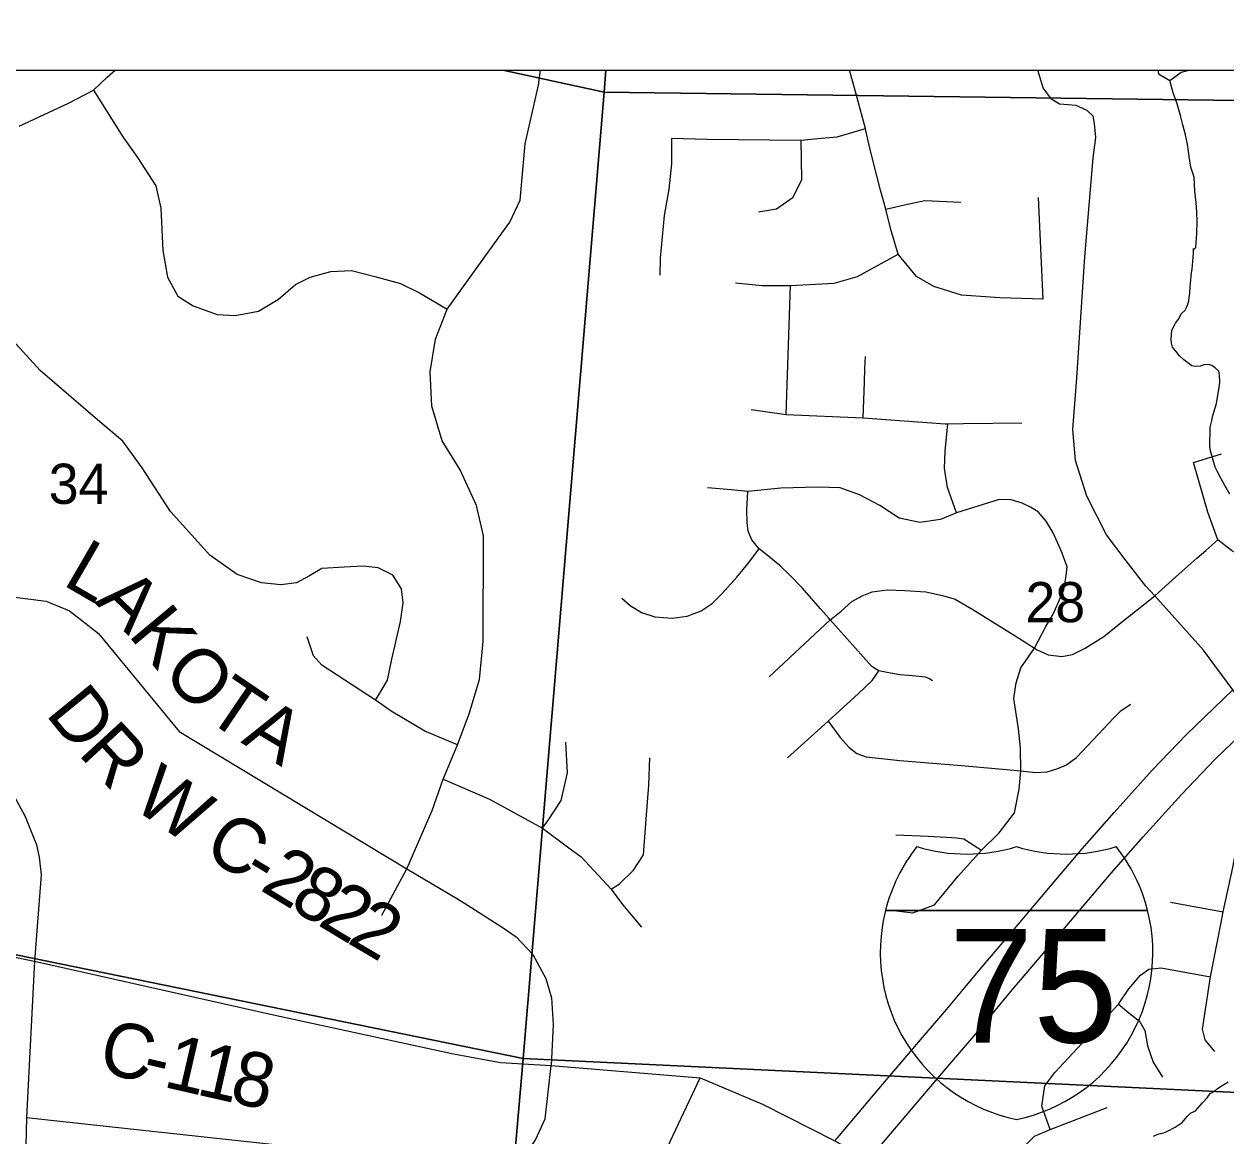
# Model space of a CAD drawing. Extents: x 0 to 34, y 0 to 22.
# Drawn here: x 6.065 to 7.317, y 17.049 to 18.207 of the extents above; entities that cross this region are included whole.
import ezdxf

# ---------------------------------------------------------------- set-up
doc = ezdxf.new("R2010")
doc.units = 0
for name, color, linetype in [('GM_X_County_Road', 7, 'Continuous'), ('GM_X_County_Road_Text', 7, 'Continuous'), ('GM_X_Interstate_Route', 7, 'Continuous'), ('GM_X_Interstate_Shield', 7, 'Continuous'), ('GM_X_Minor_River', 7, 'Continuous'), ('GM_X_Section', 7, 'Continuous'), ('GM_X_Section_Text', 7, 'Continuous'), ('GM_X_Township_Road', 7, 'Continuous'), ('SH_Text', 7, 'Continuous')]:
    doc.layers.add(name, color=color, linetype=linetype)

msp = doc.modelspace()

# ---------------------------------------------------------------- linework, layer by layer
at = {"layer": 'GM_X_County_Road'}
for points in [[(6.0466, 17.6112), (6.0876, 17.6058), (6.1121, 17.5959), (6.1422, 17.5721), (6.2262, 17.4703), (6.4637, 17.327), (6.5163, 17.296), (6.5237, 17.2912)], [(6.05, 17.4113), (6.0658, 17.3817), (6.0778, 17.352), (6.0803, 17.3393), (6.0827, 17.3208), (6.0757, 17.231), (6.0674, 17.0682), (6.0665, 17.0388)], [(5.5717, 17.3314), (5.8034, 17.2861), (6.0757, 17.231)], [(6.5237, 17.2912), (6.5628, 17.2662), (6.5774, 17.2562), (6.595, 17.2378), (6.6085, 17.213), (6.6145, 17.1929), (6.6161, 17.1648), (6.6139, 17.1224)], [(6.0757, 17.231), (6.3248, 17.175), (6.5122, 17.1344), (6.5614, 17.1253), (6.6139, 17.1224), (6.7693, 17.1094)], [(6.4586, 16.8305), (6.5073, 16.9065), (6.5468, 16.9654), (6.5664, 16.9923), (6.5837, 17.0228), (6.5978, 17.0449), (6.6079, 17.0666), (6.6139, 17.1224)], [(6.7693, 17.1094), (6.8344, 17.0818), (6.9097, 17.0436), (6.9449, 17.0241), (6.9833, 17.0009), (7.0435, 16.9721), (7.0866, 16.9621), (7.0965, 16.9604), (7.1364, 16.9551), (7.2991, 16.9477), (7.3202, 16.9415), (7.341, 16.9307), (7.382, 16.9119)]]:
    msp.add_lwpolyline(points, dxfattribs=at)
at = {"layer": 'GM_X_Interstate_Route'}
for points in [[(6.9097, 17.0436), (6.9146, 17.0494), (6.9593, 17.1023), (6.9967, 17.1464), (7.0264, 17.1809), (7.0628, 17.2247), (7.1006, 17.2692), (7.1345, 17.309), (7.1673, 17.348), (7.2008, 17.3859), (7.2405, 17.4299), (7.2758, 17.4668), (7.3245, 17.5135)], [(6.9449, 17.0241), (6.9896, 17.0769), (7.027, 17.121), (7.0568, 17.1555), (7.0931, 17.1993), (7.1309, 17.2439), (7.1648, 17.2837), (7.1976, 17.3227), (7.2311, 17.3605), (7.2708, 17.4046), (7.3061, 17.4414), (7.3481, 17.4815)]]:
    msp.add_lwpolyline(points, dxfattribs=at)
at = {"layer": 'GM_X_Interstate_Shield'}
for p, q in [((6.9624, 17.2837), (7.2357, 17.2837)), ((7.2357, 17.2837), (6.9624, 17.2837)), ((7.2357, 17.2837), (6.9624, 17.2837))]:
    msp.add_line(p, q, dxfattribs=at)
for centre, start, end in [((7.1346, 17.2401), 141.669, 165.8066), ((7.0472, 17.5201), 253.0091, 286.9909), ((7.1509, 17.5201), 253.0091, 286.9909), ((7.0635, 17.2401), 14.1934, 38.331), ((7.1346, 17.2401), 165.8066, 258.463), ((7.0635, 17.2401), 281.537, 14.1934)]:
    msp.add_arc(centre, 0.1776, start, end, dxfattribs=at)
at = {"layer": 'GM_X_Minor_River'}
for points in [[(7.2463, 18.1592), (7.2471, 18.1553), (7.2587, 18.1482)], [(7.2587, 18.1482), (7.2707, 18.157), (7.2776, 18.1587), (7.2782, 18.1592)], [(7.2834, 17.972), (7.2859, 17.9745), (7.287, 17.9889), (7.2873, 18.0015), (7.2868, 18.011), (7.2863, 18.0213), (7.2847, 18.0331), (7.2843, 18.0476), (7.2808, 18.0579), (7.2788, 18.069), (7.2772, 18.082), (7.2752, 18.0919), (7.2724, 18.1022), (7.27, 18.1118), (7.2665, 18.124), (7.2622, 18.1356), (7.2587, 18.1482)], [(7.2648, 17.8956), (7.2683, 17.9), (7.2707, 17.9053), (7.2749, 17.909), (7.2769, 17.9132), (7.2785, 17.9185), (7.279, 17.9223), (7.2795, 17.9268), (7.28, 17.9333), (7.2804, 17.9367), (7.2814, 17.9481), (7.2819, 17.9519), (7.2828, 17.9602), (7.2833, 17.9682), (7.2834, 17.972), (7.2833, 17.9733)], [(7.3213, 17.7175), (7.3162, 17.7264), (7.3118, 17.7341), (7.3082, 17.7414), (7.306, 17.7456), (7.3039, 17.7529), (7.3011, 17.7624), (7.3004, 17.767), (7.3008, 17.7872), (7.3025, 17.794), (7.3037, 17.7993), (7.3074, 17.8118), (7.3086, 17.8186), (7.3103, 17.8284), (7.3108, 17.8337), (7.3106, 17.8417), (7.3099, 17.8456), (7.3062, 17.8491), (7.3025, 17.8514), (7.2991, 17.8526), (7.2946, 17.8523), (7.2904, 17.8509), (7.2855, 17.8503), (7.2817, 17.8511), (7.2735, 17.8573), (7.2687, 17.8616), (7.265, 17.8663), (7.2617, 17.8705), (7.2606, 17.8747), (7.2603, 17.8785), (7.2604, 17.8839), (7.2609, 17.8884), (7.2648, 17.8956)], [(7.2416, 17.0486), (7.2473, 17.0512), (7.2526, 17.0522), (7.2564, 17.054), (7.2644, 17.058), (7.2717, 17.0628), (7.2768, 17.0692), (7.2802, 17.0726), (7.2856, 17.0751), (7.2929, 17.0833), (7.2976, 17.0885), (7.3007, 17.093), (7.3049, 17.0952), (7.3083, 17.0982), (7.3149, 17.1023), (7.3195, 17.1052)]]:
    msp.add_lwpolyline(points, dxfattribs=at)
at = {"layer": 'GM_X_Section'}
for points in [[(6.5636, 18.1592), (6.6692, 18.1363), (6.585, 17.1294), (5.5736, 17.336), (5.6474, 18.1592)], [(6.671, 18.1592), (6.6692, 18.1363), (6.5636, 18.1592)], [(7.7047, 18.1592), (7.7014, 18.1225), (6.6692, 18.1363), (6.671, 18.1592)], [(5.489, 16.4145), (5.5736, 17.336), (6.585, 17.1294), (6.5225, 16.4145)], [(6.5225, 16.4145), (6.585, 17.1294), (7.6063, 17.081), (7.5157, 16.0549), (7.1778, 16.0724)]]:
    msp.add_lwpolyline(points, dxfattribs=at)
msp.add_lwpolyline([(7.7014, 18.1225), (7.6063, 17.081), (6.585, 17.1294), (6.6692, 18.1363)], close=True, dxfattribs=at)
at = {"layer": 'GM_X_Township_Road'}
for p, q in [((6.9287, 18.1456), (6.925, 18.1592)), ((6.8588, 17.8004), (6.8635, 17.9347)), ((7.2503, 17.6181), (7.265, 17.6312)), ((7.243, 17.6116), (7.2503, 17.6181)), ((7.2045, 17.5808), (7.243, 17.6116)), ((6.4377, 17.2789), (6.4637, 17.327)), ((7.2595, 17.2925), (7.3143, 17.2824))]:
    msp.add_line(p, q, dxfattribs=at)
for points in [[(6.0597, 18.1006), (6.1111, 18.1247), (6.137, 18.1381), (6.1512, 18.1517), (6.1595, 18.1592)], [(6.4637, 17.327), (6.4901, 17.3878), (6.5016, 17.4204), (6.5163, 17.4562), (6.5285, 17.4885), (6.5392, 17.5243), (6.543, 17.5638), (6.5434, 17.674), (6.5363, 17.7057), (6.5193, 17.7427), (6.5004, 17.7731), (6.4897, 17.809), (6.4881, 17.845), (6.4936, 17.879), (6.5057, 17.91), (6.5501, 17.9718), (6.5711, 18.0007), (6.5816, 18.0237), (6.5869, 18.0822), (6.6007, 18.1434), (6.6028, 18.1592)], [(7.243, 17.6116), (7.2336, 17.6216), (7.2133, 17.6479), (7.1928, 17.675), (7.1723, 17.7152), (7.1604, 17.7525), (7.1577, 17.7848), (7.1619, 17.8386), (7.1703, 17.9645), (7.1789, 18.0678), (7.1816, 18.0889), (7.1803, 18.1035), (7.1788, 18.111), (7.1728, 18.1172), (7.1612, 18.1222), (7.1439, 18.1236), (7.1353, 18.129), (7.1269, 18.1406), (7.1212, 18.1592)], [(6.137, 18.1381), (6.1676, 18.0895), (6.1828, 18.0682), (6.2021, 18.0387), (6.2073, 18.0154), (6.2094, 17.9711), (6.2141, 17.9433), (6.2249, 17.9236), (6.2411, 17.9136), (6.2658, 17.9045), (6.2846, 17.9034), (6.309, 17.9081), (6.3297, 17.9207), (6.3476, 17.9357), (6.3628, 17.9433), (6.3845, 17.9493), (6.406, 17.9504), (6.4302, 17.9441), (6.4569, 17.937), (6.4768, 17.9273), (6.5057, 17.91)], [(6.9419, 18.0964), (6.9415, 18.0984), (6.9287, 18.1456)], [(6.7277, 17.9455), (6.7279, 17.9633), (6.7322, 18.0078), (6.7369, 18.0353), (6.7397, 18.0616), (6.7398, 18.0883)], [(6.7398, 18.0883), (6.7766, 18.0873), (6.8745, 18.086), (6.8953, 18.0881), (6.912, 18.0898), (6.9415, 18.0984)], [(7.1214, 18.0264), (7.1263, 17.9205), (7.0815, 17.9219), (7.0415, 17.9248), (7.0128, 17.9339), (6.9949, 17.944), (6.9757, 17.9675), (6.9718, 17.9802), (6.9681, 17.9931), (6.9628, 18.0143), (6.9571, 18.034), (6.9534, 18.049), (6.9463, 18.078), (6.9419, 18.0964)], [(6.8301, 18.0115), (6.849, 18.0145), (6.8662, 18.0269), (6.8752, 18.0451), (6.8745, 18.086)], [(6.9628, 18.0143), (6.9824, 18.0189), (7.0035, 18.0232), (7.0408, 18.0216)], [(6.8061, 17.9377), (6.8339, 17.9349), (6.8635, 17.9347), (6.9088, 17.9371), (6.9333, 17.944), (6.9757, 17.9675)], [(6.4308, 17.5027), (6.4356, 17.5101), (6.4436, 17.5238), (6.4479, 17.5454), (6.457, 17.5849), (6.4599, 17.6041), (6.458, 17.6188), (6.449, 17.633), (6.4337, 17.6405), (6.418, 17.6423), (6.3982, 17.6415), (6.375, 17.6399), (6.3622, 17.6325), (6.3485, 17.6252), (6.3322, 17.6228), (6.312, 17.625), (6.2869, 17.6338), (6.2583, 17.6538), (6.2173, 17.6994), (6.1879, 17.7448), (6.1677, 17.7726), (6.1436, 17.7928), (6.0815, 17.8463), (6.0531, 17.8775)], [(6.9392, 17.797), (6.9405, 17.8342), (6.9409, 17.8483), (6.9415, 17.8608)], [(6.8225, 17.8057), (6.8588, 17.8004), (6.9392, 17.797), (7.0245, 17.7906), (7.0275, 17.7906), (7.0436, 17.7909), (7.1046, 17.7916)], [(7.0365, 17.6978), (7.0272, 17.7244), (7.0238, 17.7445), (7.0247, 17.7622), (7.0275, 17.7906)], [(7.3535, 17.6438), (7.3394, 17.6492), (7.3232, 17.6587), (7.3088, 17.6697), (7.2983, 17.6985), (7.2835, 17.7504), (7.3128, 17.7594)], [(6.9679, 17.284), (6.991, 17.2812), (7.0135, 17.2896), (7.038, 17.319), (7.0625, 17.3464), (7.0808, 17.3646), (7.0969, 17.3856), (7.1018, 17.4102), (7.1034, 17.4291), (7.1033, 17.4531), (7.1012, 17.4728), (7.0961, 17.5046), (7.0986, 17.5207), (7.1035, 17.5366), (7.1178, 17.557), (7.1296, 17.5795), (7.1371, 17.5923), (7.1482, 17.6176), (7.1506, 17.6324), (7.1517, 17.6418), (7.1458, 17.6578), (7.1372, 17.677), (7.13, 17.6894), (7.1214, 17.699), (7.1136, 17.704), (7.1049, 17.708), (7.0935, 17.7114), (7.0808, 17.7117), (7.0365, 17.6978), (7.0197, 17.6909), (6.9984, 17.6878), (6.9767, 17.6925), (6.9565, 17.7055), (6.9355, 17.7167), (6.9153, 17.7241), (6.8915, 17.7247), (6.8533, 17.7235), (6.8191, 17.7203), (6.8016, 17.7219), (6.7771, 17.7241)], [(7.0114, 17.5229), (7.0076, 17.5254), (7.0042, 17.5268), (6.9869, 17.5286), (6.9773, 17.5293), (6.9678, 17.5308), (6.9555, 17.5333), (6.9522, 17.5354), (6.9482, 17.538), (6.9048, 17.5865), (6.903, 17.5886), (6.8946, 17.598), (6.8758, 17.6195), (6.8632, 17.6328), (6.8525, 17.6432), (6.839, 17.6537), (6.8307, 17.6605), (6.8233, 17.6698), (6.8195, 17.6788), (6.8184, 17.6878), (6.818, 17.7011), (6.8191, 17.7203)], [(7.265, 17.6312), (7.287, 17.6507), (7.2962, 17.6587), (7.3088, 17.6697)], [(6.6877, 17.6092), (6.6963, 17.6014), (6.7083, 17.5942), (6.7222, 17.5896), (6.74, 17.5882), (6.7556, 17.5904), (6.7705, 17.596), (6.7817, 17.6034), (6.7923, 17.6138), (6.8076, 17.631), (6.8191, 17.645), (6.8307, 17.6605)], [(6.8413, 17.5271), (6.9048, 17.5865), (6.9094, 17.59), (6.9163, 17.5954), (6.9274, 17.6055), (6.9382, 17.6116), (6.9485, 17.6155), (6.9642, 17.6177), (6.9826, 17.6169), (7.0045, 17.6155), (7.0217, 17.6119), (7.0351, 17.608), (7.0535, 17.5972), (7.0891, 17.5749), (7.1098, 17.5623), (7.1151, 17.5588), (7.1178, 17.557), (7.1205, 17.5552), (7.132, 17.5501), (7.1462, 17.5483), (7.1573, 17.5505), (7.1704, 17.557), (7.1899, 17.5692), (7.2045, 17.5808)], [(7.528, 17.2611), (7.502, 17.29), (7.4791, 17.318), (7.4543, 17.3478), (7.4001, 17.419), (7.3481, 17.4815), (7.3245, 17.5135), (7.2938, 17.5549), (7.243, 17.6116)], [(6.5163, 17.4562), (6.4823, 17.4706), (6.4474, 17.4915), (6.4308, 17.5027), (6.3751, 17.5391), (6.3662, 17.5489), (6.3597, 17.5688)], [(6.8604, 17.4426), (6.9027, 17.4808), (6.9066, 17.4843), (6.9344, 17.5099), (6.9487, 17.5234), (6.9555, 17.5333)], [(6.9027, 17.4808), (6.9151, 17.4639), (6.9246, 17.4535), (6.9327, 17.4474), (6.9423, 17.4438), (6.9775, 17.4398), (7.0415, 17.4348), (7.0925, 17.4301), (7.1034, 17.4291), (7.1189, 17.4276), (7.1308, 17.4283), (7.1419, 17.4315), (7.1511, 17.4355), (7.1614, 17.443), (7.1844, 17.4675), (7.2001, 17.484), (7.2082, 17.4922), (7.2181, 17.4987)], [(6.6049, 17.3694), (6.6111, 17.3782), (6.6244, 17.3982), (6.6309, 17.4272), (6.6292, 17.4591)], [(6.6765, 17.3061), (6.6853, 17.3114), (6.7, 17.3256), (6.7104, 17.3416), (6.7132, 17.3787), (6.7159, 17.4142), (6.717, 17.4429)], [(6.5016, 17.4204), (6.5499, 17.3998), (6.6049, 17.3694), (6.6311, 17.3499), (6.6452, 17.3395), (6.6765, 17.3061), (6.6882, 17.2901), (6.7083, 17.2663)], [(7.3056, 17.1369), (7.2957, 17.1489), (7.2929, 17.1601), (7.3013, 17.2147), (7.3119, 17.2694), (7.3143, 17.2824), (7.3245, 17.3286), (7.3281, 17.3488), (7.3334, 17.3616), (7.3429, 17.3756), (7.4001, 17.419)], [(6.9732, 17.3625), (7.007, 17.3611), (7.0257, 17.36), (7.0369, 17.3593), (7.0441, 17.3582), (7.0499, 17.3546), (7.0625, 17.3464)], [(7.1339, 17.0557), (7.1255, 17.0798), (7.1286, 17.1009), (7.1391, 17.1149), (7.2053, 17.1861), (7.2159, 17.2021), (7.2281, 17.2165), (7.2369, 17.2225), (7.2498, 17.2239), (7.3013, 17.2147)], [(7.2053, 17.1861), (7.2159, 17.1772), (7.2273, 17.1683), (7.2329, 17.1586), (7.2354, 17.1426), (7.2415, 17.1258), (7.2513, 17.11)], [(6.5879, 16.9397), (6.6331, 16.9115), (6.6385, 16.9093), (6.6416, 16.9081), (6.6474, 16.9077), (6.6526, 16.9074), (6.6557, 16.9086), (6.6609, 16.9137), (6.6682, 16.921), (6.7186, 17.0016), (6.7693, 17.1094)], [(7.0866, 16.9621), (7.0996, 17.0203), (7.1073, 17.0381), (7.1177, 17.0488), (7.1339, 17.0557), (7.1934, 17.0784)], [(6.0674, 17.0682), (6.1534, 17.0586), (6.3069, 17.0421), (6.4389, 17.0278), (6.4681, 17.0174), (6.5046, 16.9934), (6.5468, 16.9654)]]:
    msp.add_lwpolyline(points, dxfattribs=at)
at = {"layer": 'SH_Text'}
msp.add_lwpolyline([(8.8041, 18.7255), (5.1102, 18.7255), (5.1102, 18.1592), (8.8041, 18.1592)], close=True, dxfattribs=at)

# ---------------------------------------------------------------- texts
at = {"layer": 'GM_X_County_Road_Text'}
for s, rotation, p in [('L', 329.8822, (6.1036, 17.6237)), ('A', 315.9518, (6.1374, 17.6046)), ('K', 309.8284, (6.1723, 17.571)), ('O', 313.5206, (6.207, 17.5296)), ('T', 325.8443, (6.2516, 17.4847)), ('D', 309.1606, (6.0861, 17.4885)), ('A', 329.2654, (6.2899, 17.4589)), ('R', 312.5454, (6.12, 17.447)), ('W', 326.0845, (6.1757, 17.3918)), ('C', 328.737, (6.2495, 17.342)), ('-', 328.7344, (6.2894, 17.3178)), ('2', 328.7482, (6.3094, 17.3057)), ('8', 328.784, (6.3394, 17.2875)), ('2', 328.9214, (6.3694, 17.2693)), ('2', 329.6243, (6.4, 17.2508)), ('C', 347.007, (6.1403, 17.1161)), ('1', 347.053, (6.2085, 17.1003)), ('1', 347.206, (6.2428, 17.0924)), ('8', 347.7796, (6.2775, 17.0845)), ('-', 347.0166, (6.1857, 17.1056))]:
    msp.add_text(s, height=0.0568, rotation=rotation, dxfattribs=at).set_placement(p)
at = {"layer": 'GM_X_Interstate_Shield'}
msp.add_text('75', height=0.11837, dxfattribs=at).set_placement((7.0284, 17.1461))
at = {"layer": 'GM_X_Section_Text'}
for s, p in [('34', (6.0904, 17.7073)), ('28', (7.1083, 17.584))]:
    msp.add_text(s, height=0.04186, rotation=0, dxfattribs=at).set_placement(p)

doc.saveas('drawing.dxf')
